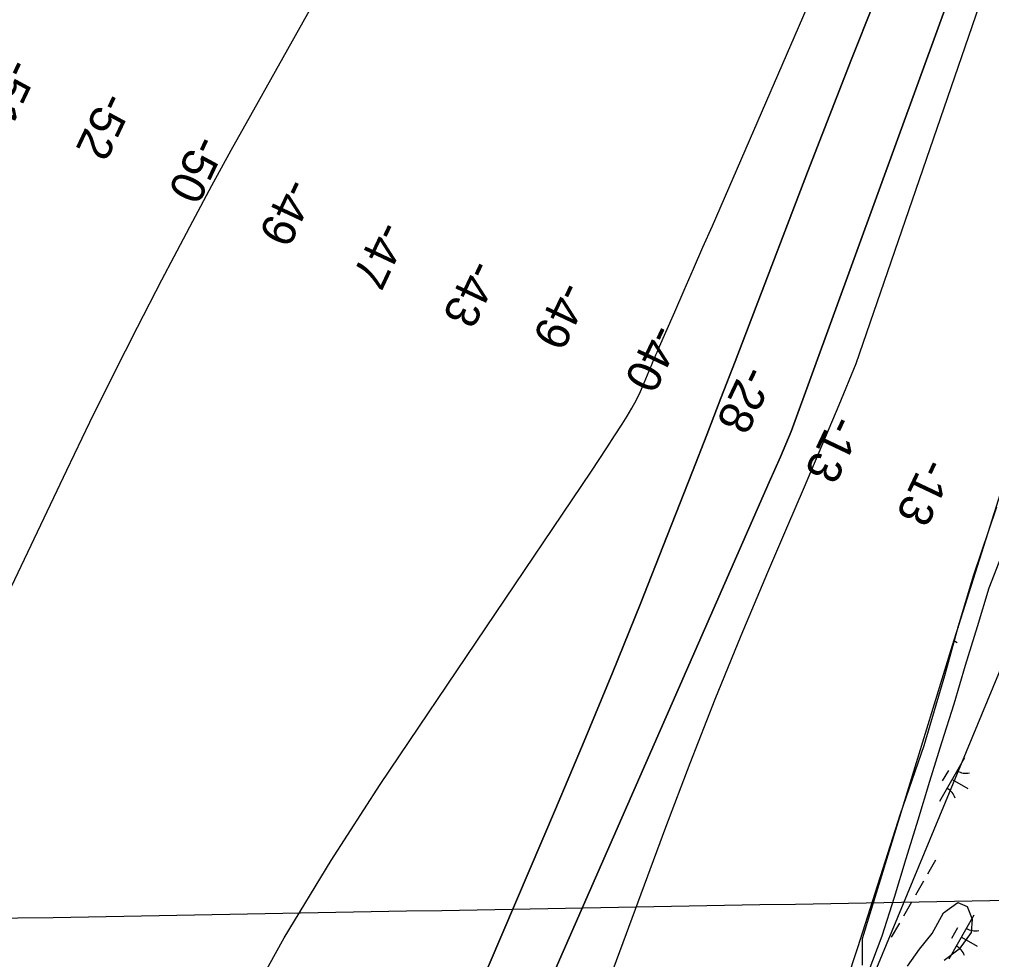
# Model space of a CAD drawing. Extents: x 3930721 to 3950824, y 220441 to 242861.
# Drawn here: x 3938420 to 3939382, y 224073 to 225003 of the extents above; entities that cross this region are included whole.
import ezdxf

# ---------------------------------------------------------------- set-up
doc = ezdxf.new("R2010")
doc.units = 0
for name, color, linetype in [('V-GRID-MAJR', 7, 'Continuous'), ('V-RIVR-EDGE', 7, 'Continuous'), ('V-RIVR-RANG', 7, 'Continuous'), ('V-RRAP-FSHR', 7, 'Continuous'), ('V-TOPO-DPTH', 7, 'Continuous'), ('V-TOPO-MAJR', 7, 'Continuous'), ('V-TOPO-MINR', 7, 'Continuous'), ('V-UTIL-LINE', 7, 'Continuous'), ('V-WETL-SWMP', 7, 'Continuous')]:
    doc.layers.add(name, color=color, linetype=linetype)

msp = doc.modelspace()

# ---------------------------------------------------------------- linework, layer by layer
at = {"layer": 'V-GRID-MAJR'}
msp.add_spline([(3936389.65, 224077.73), (3940866.25, 224158.18), (3943106.43, 224198.66)], degree=3, dxfattribs=at)
at = {"layer": 'V-RIVR-EDGE'}
for points in [[(3939645.72, 225105.63), (3939564.64, 224973.39), (3939519.78, 224883.65), (3939452.87, 224704.97), (3939394.62, 224547.53), (3939342.66, 224383.8), (3939253.72, 224093.34), (3939253.72, 224067.36)], [(3939298.58, 224066.58), (3939310.39, 224083.11), (3939322.99, 224098.85), (3939334.01, 224119.32), (3939348.17, 224129.55), (3939357.62, 224125.61), (3939362.34, 224113.02), (3939361.56, 224099.64), (3939349.75, 224083.11), (3939334.79, 224072.09)]]:
    msp.add_lwpolyline(points, dxfattribs=at)
at = {"layer": 'V-RRAP-FSHR'}
msp.add_lwpolyline([(3939259.66, 224059.9), (3939273.48, 224096.62), (3939285.52, 224134.76), (3939297.21, 224173.13), (3939308.9, 224211.27), (3939320.59, 224249.52), (3939332.3, 224287.77), (3939344.7, 224326), (3939355.83, 224364.23), (3939367.6, 224402.46), (3939379.36, 224440.69), (3939393.67, 224478.16)], dxfattribs=at)
at = {"layer": 'V-TOPO-DPTH'}
for points in [[(3939914.93, 226384.46), (3939698.07, 225912.33), (3939668.88, 225848.66), (3939639.75, 225784.95), (3939610.72, 225721.2), (3939581.76, 225657.42), (3939532.95, 225549.74), (3939528.48, 225539.76), (3939524.05, 225529.76), (3939519.7, 225519.72), (3939183.49, 224595.65), (3939172.69, 224570.46), (3939161.75, 224545.31), (3938861.77, 223862.19), (3938846.99, 223828.49), (3938832.24, 223794.76), (3938819.02, 223764.41)], [(3938766.8, 223792.47), (3938950.29, 224221.96), (3938978.67, 224289.25), (3939006.62, 224356.72), (3939033.95, 224424.44), (3939060.85, 224492.33), (3939085.74, 224556), (3939099.84, 224592.2), (3939113.89, 224628.43), (3939127.85, 224664.68), (3939141.76, 224700.96), (3939199.55, 224852.24), (3939242.95, 224963.92), (3939287.2, 225075.25), (3939332.72, 225186.07), (3939379.09, 225296.55), (3939461.4, 225489.54), (3939473.96, 225518.77), (3939486.62, 225547.96), (3939499.43, 225577.08), (3939512.35, 225606.16), (3939815.82, 226284.77)], [(3939815.82, 226284.77), (3939512.35, 225606.16), (3939499.43, 225577.08), (3939486.62, 225547.96), (3939473.96, 225518.77), (3939461.4, 225489.54), (3939379.09, 225296.55), (3939332.72, 225186.07), (3939287.2, 225075.25), (3939242.95, 224963.92), (3939199.55, 224852.24), (3939141.76, 224700.96), (3939127.85, 224664.68), (3939113.89, 224628.43), (3939099.84, 224592.2), (3939085.74, 224556), (3939060.85, 224492.33), (3939033.95, 224424.44), (3939006.62, 224356.72), (3938978.67, 224289.25), (3938950.29, 224221.96), (3938766.8, 223792.47)], [(3938638.46, 224016.43), (3938681.88, 224094.57), (3938728.36, 224170.94), (3938776.88, 224246.12), (3938985.77, 224556.23), (3938993.5, 224567.83), (3939001.15, 224579.47), (3939008.68, 224591.18), (3939016.13, 224602.95), (3939021.08, 224610.85), (3939025.8, 224618.81), (3939030.23, 224626.92), (3939034.25, 224635.24), (3939037.99, 224643.7), (3939042.85, 224655.48), (3939043.96, 224658.16), (3939045.07, 224660.84), (3939046.19, 224663.51), (3939047.32, 224666.18), (3939048.45, 224668.85), (3939049.59, 224671.52), (3939050.75, 224674.18), (3939051.91, 224676.84), (3939068.25, 224714.06), (3939077.57, 224735.33), (3939086.88, 224756.61), (3939096.15, 224777.91), (3939105.41, 224799.21), (3939362.93, 225392.98)], [(3938638.46, 224016.43), (3938681.88, 224094.57), (3938728.36, 224170.94), (3938776.88, 224246.12), (3938985.77, 224556.23), (3938993.5, 224567.83), (3939001.15, 224579.47), (3939008.68, 224591.18), (3939016.13, 224602.95), (3939021.08, 224610.85), (3939025.8, 224618.81), (3939030.23, 224626.92), (3939034.25, 224635.24), (3939037.99, 224643.7), (3939042.85, 224655.48), (3939043.96, 224658.16), (3939045.07, 224660.84), (3939046.19, 224663.51), (3939047.32, 224666.18), (3939048.45, 224668.85), (3939049.59, 224671.52), (3939050.75, 224674.18), (3939051.91, 224676.84), (3939068.25, 224714.06), (3939077.57, 224735.33), (3939086.88, 224756.61), (3939096.15, 224777.91), (3939105.41, 224799.21), (3939362.93, 225392.98)]]:
    msp.add_lwpolyline(points, dxfattribs=at)
at = {"layer": 'V-TOPO-MAJR'}
msp.add_lwpolyline([(3938237.81, 224076.66), (3938466.64, 224557.18), (3938489.57, 224604.65), (3938512.86, 224651.93), (3938536.67, 224698.96), (3938560.84, 224745.8), (3938572.81, 224768.68), (3938591.41, 224803.87), (3938610.21, 224838.95), (3938629.32, 224873.87), (3938648.63, 224908.67), (3938882.03, 225325.01), (3938918.31, 225390.32), (3938954.25, 225455.81), (3938989.69, 225521.57), (3939024.8, 225587.52), (3939082.34, 225696.62), (3939088.4, 225708.17), (3939094.42, 225719.73), (3939100.4, 225731.32), (3939106.35, 225742.93), (3939376.33, 226272.71)], dxfattribs=at)
at = {"layer": 'V-TOPO-MINR'}
for points in [[(3938819.02, 223764.41), (3938832.24, 223794.76), (3938846.99, 223828.49), (3938861.77, 223862.19), (3939161.75, 224545.31), (3939172.69, 224570.46), (3939183.49, 224595.65), (3939519.7, 225519.72), (3939524.05, 225529.76), (3939528.48, 225539.76), (3939532.95, 225549.74), (3939581.76, 225657.42), (3939610.72, 225721.2), (3939639.75, 225784.95), (3939668.88, 225848.66), (3939698.07, 225912.33), (3939914.93, 226384.46)], [(3938766.8, 223792.47), (3938950.29, 224221.96), (3938978.67, 224289.25), (3939006.62, 224356.72), (3939033.95, 224424.44), (3939060.85, 224492.33), (3939085.74, 224556), (3939099.84, 224592.2), (3939113.89, 224628.43), (3939127.85, 224664.68), (3939141.76, 224700.96), (3939199.55, 224852.24), (3939242.95, 224963.92), (3939287.2, 225075.25), (3939332.72, 225186.07), (3939379.09, 225296.55), (3939461.4, 225489.54), (3939473.96, 225518.77), (3939486.62, 225547.96), (3939499.43, 225577.08), (3939512.35, 225606.16), (3939815.82, 226284.77)], [(3938883.81, 223729.61), (3939059.46, 224203.88), (3939083.56, 224267.45), (3939108.3, 224330.76), (3939134, 224393.68), (3939160.35, 224456.35), (3939179.2, 224500.24), (3939196.52, 224540.81), (3939213.73, 224581.42), (3939230.79, 224622.09), (3939247.73, 224662.82), (3939536.86, 225503.8)], [(3938638.46, 224016.43), (3938681.88, 224094.57), (3938728.36, 224170.94), (3938776.88, 224246.12), (3938985.77, 224556.23), (3938993.5, 224567.83), (3939001.15, 224579.47), (3939008.68, 224591.18), (3939016.13, 224602.95), (3939021.08, 224610.85), (3939025.8, 224618.81), (3939030.23, 224626.92), (3939034.25, 224635.24), (3939037.99, 224643.7), (3939042.85, 224655.48), (3939043.96, 224658.16), (3939045.07, 224660.84), (3939046.19, 224663.51), (3939047.32, 224666.18), (3939048.45, 224668.85), (3939049.59, 224671.52), (3939050.75, 224674.18), (3939051.91, 224676.84), (3939068.25, 224714.06), (3939077.57, 224735.33), (3939086.88, 224756.61), (3939096.15, 224777.91), (3939105.41, 224799.21), (3939362.93, 225392.98)]]:
    msp.add_lwpolyline(points, dxfattribs=at)
at = {"layer": 'V-UTIL-LINE'}
msp.add_lwpolyline([(3947453.78, 235874.4), (3945931.14, 235655.08), (3945509.06, 234777.68), (3940428.61, 226869.1), (3939084.62, 223621.72)], dxfattribs=at)
at = {"layer": 'V-WETL-SWMP'}
for p, q in [((3939363.88, 224452.75), (3939386.99, 224520.85)), ((3939348.97, 224403.31), (3939363.88, 224452.75)), ((3939335.47, 224354.08), (3939348.97, 224403.31)), ((3939344.87, 224388.34), (3939347.76, 224386.69)), ((3939315, 224284.78), (3939335.47, 224354.08)), ((3939291.49, 224217.08), (3939315, 224284.78)), ((3939355.03, 224272.77), (3939330.19, 224229.38)), ((3939338.9, 224260.11), (3939332.93, 224249.7)), ((3939342.61, 224251.07), (3939358.23, 224242.13)), ((3939249.5, 224084.75), (3939291.49, 224217.08)), ((3939326.21, 224171.39), (3939318.26, 224157.51)), ((3939314.28, 224150.56), (3939306.33, 224136.68)), ((3939302.36, 224129.74), (3939294.41, 224115.85)), ((3939364.18, 224116.89), (3939339.33, 224073.5)), ((3939290.43, 224108.91), (3939282.48, 224095.03)), ((3939348.05, 224104.24), (3939342.08, 224093.82)), ((3939351.76, 224095.2), (3939367.38, 224086.25)), ((3939217.62, 223990.5), (3939249.5, 224084.75))]:
    msp.add_line(p, q, dxfattribs=at)
for centre, start, end in [((3939346.07, 224419.48), 278.3379, 280.97154), ((3939356.54, 224274.92), 239.42788, 280.97154), ((3939329.09, 224226.99), 19.42788, 60.97154), ((3939365.69, 224119.05), 239.42788, 280.97154), ((3939338.24, 224071.11), 19.42788, 60.97154)]:
    msp.add_arc(centre, 17.62, start, end, dxfattribs=at)

# ---------------------------------------------------------------- texts
at = {"layer": 'V-RIVR-RANG'}
for s, rotation, p in [('-51', 244.78747, (3938408.72, 224967.13)), ('-52', 244.78747, (3938502.52, 224933.72)), ('-50', 244.78747, (3938593.92, 224891.25)), ('-49', 244.78747, (3938683.68, 224848.8)), ('-47', 244.78747, (3938775.28, 224806.26)), ('-43', 244.78747, (3938865.74, 224768.12)), ('-49', 244.64833, (3938954.82, 224746.52)), ('-40', 244.64833, (3939045.52, 224704.4)), ('-28', 244.64833, (3939136.62, 224663.11)), ('-13', 244.64833, (3939224.04, 224614.08)), ('-13', 244.64833, (3939314.52, 224571.48))]:
    msp.add_text(s, height=33.5, rotation=rotation, dxfattribs=at).set_placement(p)

doc.saveas('drawing.dxf')
